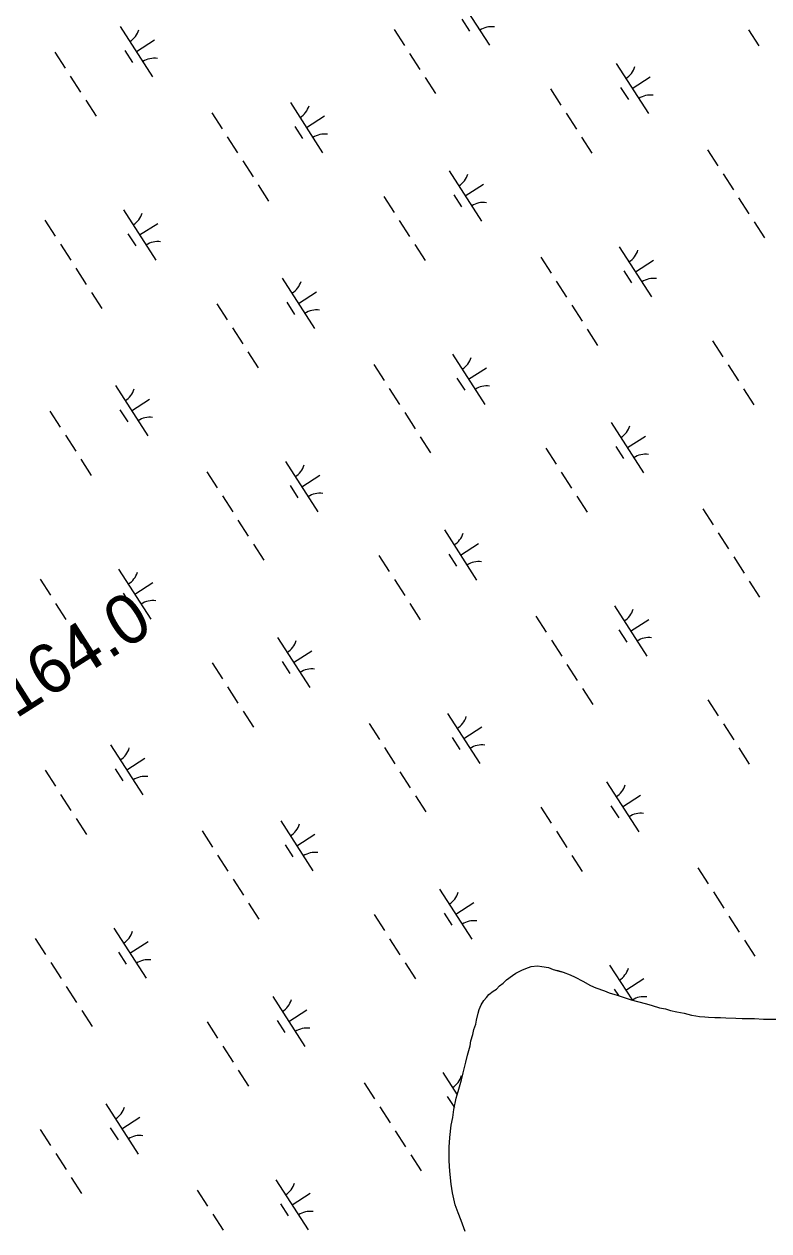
# Model space of a CAD drawing. Extents: x 3937982 to 3958556, y 219448 to 241894.
# Drawn here: x 3952246 to 3952870, y 224641 to 225653 of the extents above; entities that cross this region are included whole.
import ezdxf

# ---------------------------------------------------------------- set-up
doc = ezdxf.new("R2010")
doc.units = 0
for name, color, linetype in [('V-RIVR-RANG-IDEN', 7, 'Continuous'), ('V-TOPO-SHOR', 7, 'Continuous'), ('V-WETL-SWMP', 7, 'Continuous')]:
    doc.layers.add(name, color=color, linetype=linetype)

msp = doc.modelspace()

# ---------------------------------------------------------------- linework, layer by layer
at = {"layer": 'V-TOPO-SHOR'}
for points in [[(3952615.807, 224640.558), (3952612.462, 224649.753), (3952609.79, 224656.321), (3952607.449, 224662.889), (3952605.083, 224673.08), (3952604.053, 224680.314), (3952603.003, 224691.17), (3952602.294, 224699.722), (3952602.226, 224711.242), (3952602.837, 224719.473), (3952604.092, 224729.685), (3952605.37, 224736.275), (3952606.32, 224742.864), (3952608.239, 224752.42), (3952609.851, 224758.025), (3952612.757, 224767.587), (3952614.039, 224773.518), (3952616.292, 224782.419), (3952617.572, 224788.352), (3952619.831, 224796.263), (3952620.464, 224800.545), (3952622.078, 224805.821), (3952623.042, 224809.778), (3952624.66, 224814.394), (3952625.299, 224817.689), (3952626.581, 224823.62), (3952627.552, 224826.59), (3952629.174, 224830.549), (3952631.457, 224834.182), (3952633.745, 224836.83), (3952635.705, 224839.144), (3952639.309, 224842.128), (3952641.933, 224843.789), (3952644.55, 224846.437), (3952647.499, 224848.757), (3952650.446, 224851.41), (3952655.362, 224855.057), (3952658.313, 224857.05), (3952663.232, 224859.712), (3952666.517, 224861.048), (3952671.115, 224862.721)], [(3952671.115, 224862.721), (3952676.376, 224863.411), (3952680.001, 224862.774), (3952685.602, 224861.818), (3952689.561, 224860.196), (3952693.518, 224859.233), (3952697.802, 224857.941), (3952703.742, 224855.672), (3952708.03, 224853.722), (3952714.303, 224850.468), (3952720.908, 224846.886), (3952725.198, 224844.936), (3952732.455, 224842.345), (3952736.413, 224840.723), (3952743.008, 224838.788), (3952747.296, 224837.166), (3952754.878, 224834.907), (3952760.156, 224833.293), (3952767.735, 224831.362), (3952772.352, 224830.072), (3952778.616, 224828.134), (3952783.56, 224827.176), (3952787.847, 224825.883), (3952793.12, 224824.599), (3952799.379, 224823.649), (3952805.312, 224822.037), (3952808.937, 224821.4), (3952812.232, 224820.761), (3952816.513, 224820.456), (3952819.806, 224820.147), (3952825.073, 224819.85), (3952829.681, 224819.877), (3952834.291, 224819.573), (3952842.52, 224819.293), (3952847.79, 224818.996), (3952858.321, 224819.057), (3952865.894, 224818.443), (3952876.097, 224818.502)]]:
    msp.add_lwpolyline(points, dxfattribs=at)
at = {"layer": 'V-WETL-SWMP'}
for p, q in [((3952609.077, 225677.051), (3952636.14, 225635.007)), ((3952612.873, 225656.898), (3952619.368, 225646.808)), ((3952326.644, 225650.711), (3952353.707, 225608.668)), ((3952556.202, 225648.275), (3952564.862, 225634.821)), ((3952853.188, 225648.023), (3952861.848, 225634.569)), ((3952340.175, 225629.69), (3952355.311, 225639.432)), ((3952271.778, 225629.314), (3952280.438, 225615.86)), ((3952330.44, 225630.559), (3952336.935, 225620.468)), ((3952569.192, 225628.094), (3952577.852, 225614.64)), ((3952742.207, 225619.752), (3952769.269, 225577.709)), ((3952284.768, 225609.133), (3952293.428, 225595.68)), ((3952582.182, 225607.913), (3952590.842, 225594.46)), ((3952755.738, 225598.73), (3952770.873, 225608.473)), ((3952687.341, 225598.355), (3952696.001, 225584.901)), ((3952746.003, 225599.6), (3952752.498, 225589.509)), ((3952297.758, 225588.953), (3952306.418, 225575.499)), ((3952469.21, 225587.021), (3952496.273, 225544.978)), ((3952403.345, 225578.426), (3952412.005, 225564.972)), ((3952482.741, 225565.999), (3952497.877, 225575.742)), ((3952700.331, 225578.174), (3952708.99, 225564.72)), ((3952473.006, 225566.869), (3952479.501, 225556.778)), ((3952416.335, 225558.245), (3952424.995, 225544.792)), ((3952713.32, 225557.993), (3952721.98, 225544.54)), ((3952818.908, 225547.467), (3952827.568, 225534.013)), ((3952429.325, 225538.065), (3952437.985, 225524.611)), ((3952602.339, 225529.722), (3952629.402, 225487.679)), ((3952831.897, 225527.286), (3952840.557, 225513.832)), ((3952442.315, 225517.884), (3952450.975, 225504.43)), ((3952615.871, 225508.701), (3952631.006, 225518.443)), ((3952547.473, 225508.325), (3952556.133, 225494.872)), ((3952606.135, 225509.57), (3952612.63, 225499.48)), ((3952844.887, 225507.105), (3952853.547, 225493.652)), ((3952329.343, 225496.992), (3952356.405, 225454.948)), ((3952263.478, 225488.397), (3952272.138, 225474.943)), ((3952342.874, 225475.97), (3952358.01, 225485.712)), ((3952560.463, 225488.145), (3952569.123, 225474.691)), ((3952857.877, 225486.925), (3952866.537, 225473.471)), ((3952333.139, 225476.839), (3952339.634, 225466.749)), ((3952276.468, 225468.216), (3952285.128, 225454.762)), ((3952573.453, 225467.964), (3952582.113, 225454.51)), ((3952744.905, 225466.032), (3952771.968, 225423.989)), ((3952679.04, 225457.437), (3952687.7, 225443.984)), ((3952758.436, 225445.011), (3952773.572, 225454.753)), ((3952289.458, 225448.035), (3952298.118, 225434.581)), ((3952748.701, 225445.88), (3952755.196, 225435.79)), ((3952462.472, 225439.693), (3952489.534, 225397.65)), ((3952692.03, 225437.257), (3952700.69, 225423.803)), ((3952302.448, 225427.854), (3952311.108, 225414.401)), ((3952476.003, 225418.671), (3952491.139, 225428.414)), ((3952407.606, 225418.296), (3952416.266, 225404.842)), ((3952466.268, 225419.541), (3952472.763, 225409.45)), ((3952705.02, 225417.076), (3952713.68, 225403.622)), ((3952420.596, 225398.115), (3952429.256, 225384.661)), ((3952718.01, 225396.895), (3952726.67, 225383.441)), ((3952823.168, 225387.337), (3952831.828, 225373.883)), ((3952433.586, 225377.934), (3952442.246, 225364.481)), ((3952605.038, 225376.003), (3952632.1, 225333.96)), ((3952539.173, 225367.408), (3952547.833, 225353.954)), ((3952618.569, 225354.981), (3952633.705, 225364.724)), ((3952836.158, 225367.156), (3952844.818, 225353.702)), ((3952608.834, 225355.85), (3952615.329, 225345.76)), ((3952322.605, 225349.663), (3952349.667, 225307.62)), ((3952552.163, 225347.227), (3952560.823, 225333.773)), ((3952849.148, 225346.975), (3952857.808, 225333.521)), ((3952336.136, 225328.642), (3952351.272, 225338.384)), ((3952267.739, 225328.266), (3952276.399, 225314.813)), ((3952326.401, 225329.511), (3952332.896, 225319.421)), ((3952565.153, 225327.046), (3952573.813, 225313.593)), ((3952738.167, 225318.704), (3952765.23, 225276.661)), ((3952280.729, 225308.086), (3952289.389, 225294.632)), ((3952578.143, 225306.866), (3952586.803, 225293.412)), ((3952751.698, 225297.683), (3952766.834, 225307.425)), ((3952683.301, 225297.307), (3952691.961, 225283.853)), ((3952741.963, 225298.552), (3952748.458, 225288.461)), ((3952293.719, 225287.905), (3952302.379, 225274.451)), ((3952465.171, 225285.973), (3952492.233, 225243.93)), ((3952399.306, 225277.378), (3952407.966, 225263.925)), ((3952478.702, 225264.952), (3952493.837, 225274.694)), ((3952696.291, 225277.126), (3952704.951, 225263.673)), ((3952468.967, 225265.821), (3952475.462, 225255.731)), ((3952412.296, 225257.198), (3952420.956, 225243.744)), ((3952709.281, 225256.946), (3952717.941, 225243.492)), ((3952814.868, 225246.419), (3952823.528, 225232.965)), ((3952425.286, 225237.017), (3952433.946, 225223.563)), ((3952598.3, 225228.675), (3952625.362, 225186.632)), ((3952827.858, 225226.238), (3952836.518, 225212.785)), ((3952438.275, 225216.836), (3952446.935, 225203.382)), ((3952611.831, 225207.653), (3952626.967, 225217.396)), ((3952543.434, 225207.278), (3952552.094, 225193.824)), ((3952602.096, 225208.522), (3952608.591, 225198.432)), ((3952840.848, 225206.058), (3952849.508, 225192.604)), ((3952325.304, 225195.944), (3952352.366, 225153.901)), ((3952259.439, 225187.349), (3952268.098, 225173.895)), ((3952338.835, 225174.922), (3952353.97, 225184.665)), ((3952556.424, 225187.097), (3952565.084, 225173.643)), ((3952853.838, 225185.877), (3952862.498, 225172.423)), ((3952329.1, 225175.791), (3952335.594, 225165.701)), ((3952272.428, 225167.168), (3952281.088, 225153.714)), ((3952569.414, 225166.916), (3952578.074, 225153.462)), ((3952740.866, 225164.985), (3952767.928, 225122.941)), ((3952675.001, 225156.39), (3952683.661, 225142.936)), ((3952754.397, 225143.963), (3952769.533, 225153.705)), ((3952285.418, 225146.987), (3952294.078, 225133.534)), ((3952458.433, 225138.645), (3952485.495, 225096.602)), ((3952744.662, 225144.832), (3952751.157, 225134.742)), ((3952687.991, 225136.209), (3952696.651, 225122.755)), ((3952298.408, 225126.807), (3952307.068, 225113.353)), ((3952462.229, 225118.493), (3952468.724, 225108.402)), ((3952471.964, 225117.624), (3952487.099, 225127.366)), ((3952403.567, 225117.248), (3952412.227, 225103.794)), ((3952700.981, 225116.028), (3952709.641, 225102.574)), ((3952416.557, 225097.067), (3952425.217, 225083.614)), ((3952713.971, 225095.847), (3952722.631, 225082.394)), ((3952819.129, 225086.289), (3952827.789, 225072.835)), ((3952429.547, 225076.887), (3952438.206, 225063.433)), ((3952600.999, 225074.955), (3952628.061, 225032.912)), ((3952535.134, 225066.36), (3952543.794, 225052.906)), ((3952614.53, 225053.933), (3952629.665, 225063.676)), ((3952832.119, 225066.108), (3952840.779, 225052.654)), ((3952318.565, 225048.616), (3952345.628, 225006.572)), ((3952604.795, 225054.803), (3952611.29, 225044.712)), ((3952332.097, 225027.594), (3952347.232, 225037.337)), ((3952548.124, 225046.179), (3952556.783, 225032.726)), ((3952845.109, 225045.927), (3952853.769, 225032.474)), ((3952263.699, 225027.219), (3952272.359, 225013.765)), ((3952322.361, 225028.463), (3952328.856, 225018.373)), ((3952561.113, 225025.999), (3952569.773, 225012.545)), ((3952734.128, 225017.656), (3952761.19, 224975.613)), ((3952276.689, 225007.038), (3952285.349, 224993.584)), ((3952747.659, 224996.635), (3952762.795, 225006.377)), ((3952574.103, 225005.818), (3952582.763, 224992.364)), ((3952679.262, 224996.259), (3952687.922, 224982.806)), ((3952737.924, 224997.504), (3952744.419, 224987.414)), ((3952289.679, 224986.857), (3952298.339, 224973.403)), ((3952395.266, 224976.331), (3952403.926, 224962.877)), ((3952461.131, 224984.926), (3952488.194, 224942.882)), ((3952692.252, 224976.079), (3952700.912, 224962.625)), ((3952474.663, 224963.904), (3952489.798, 224973.646)), ((3952408.256, 224956.15), (3952416.916, 224942.696)), ((3952464.927, 224964.773), (3952471.422, 224954.683)), ((3952705.242, 224955.898), (3952713.902, 224942.444)), ((3952421.246, 224935.969), (3952429.906, 224922.515)), ((3952810.829, 224945.371), (3952819.489, 224931.918)), ((3952594.261, 224927.627), (3952621.323, 224885.584)), ((3952434.236, 224915.788), (3952442.896, 224902.335)), ((3952607.792, 224906.605), (3952622.927, 224916.348)), ((3952823.819, 224925.191), (3952832.479, 224911.737)), ((3952539.395, 224906.23), (3952548.054, 224892.776)), ((3952598.057, 224907.475), (3952604.552, 224897.384)), ((3952836.809, 224905.01), (3952845.468, 224891.556)), ((3952255.399, 224886.301), (3952264.059, 224872.847)), ((3952321.264, 224894.896), (3952348.326, 224852.853)), ((3952552.384, 224886.049), (3952561.044, 224872.595)), ((3952334.795, 224873.874), (3952349.931, 224883.617)), ((3952849.798, 224884.829), (3952858.458, 224871.375)), ((3952268.389, 224866.12), (3952277.049, 224852.667)), ((3952325.06, 224874.744), (3952331.555, 224864.653)), ((3952565.374, 224865.868), (3952574.034, 224852.415)), ((3952650.446, 224851.409), (3952655.361, 224855.058)), ((3952655.361, 224855.058), (3952658.312, 224857.05)), ((3952658.312, 224857.05), (3952663.233, 224859.712)), ((3952663.233, 224859.712), (3952666.517, 224861.048)), ((3952666.517, 224861.048), (3952671.115, 224862.721)), ((3952671.115, 224862.721), (3952676.377, 224863.41)), ((3952676.377, 224863.41), (3952680.001, 224862.773)), ((3952680.001, 224862.773), (3952685.602, 224861.818)), ((3952685.602, 224861.818), (3952689.561, 224860.196)), ((3952689.561, 224860.196), (3952693.517, 224859.232)), ((3952693.517, 224859.232), (3952697.803, 224857.94)), ((3952697.803, 224857.94), (3952703.741, 224855.671)), ((3952703.741, 224855.671), (3952708.031, 224853.722)), ((3952736.826, 224863.937), (3952755.668, 224834.666)), ((3952281.379, 224845.94), (3952290.039, 224832.486)), ((3952641.933, 224843.789), (3952644.55, 224846.437)), ((3952644.55, 224846.437), (3952647.499, 224848.758)), ((3952647.499, 224848.758), (3952650.446, 224851.409)), ((3952708.031, 224853.722), (3952714.304, 224850.467)), ((3952714.304, 224850.467), (3952720.908, 224846.885)), ((3952720.908, 224846.885), (3952725.198, 224844.936)), ((3952725.198, 224844.936), (3952732.454, 224842.345)), ((3952750.358, 224842.915), (3952765.493, 224852.658)), ((3952454.393, 224837.597), (3952481.456, 224795.554)), ((3952631.457, 224834.182), (3952633.745, 224836.829)), ((3952633.745, 224836.829), (3952635.706, 224839.144)), ((3952635.706, 224839.144), (3952639.309, 224842.128)), ((3952639.309, 224842.128), (3952641.933, 224843.789)), ((3952732.454, 224842.345), (3952736.413, 224840.723)), ((3952736.413, 224840.723), (3952743.007, 224838.787)), ((3952740.622, 224843.784), (3952744.107, 224838.371)), ((3952743.007, 224838.787), (3952747.296, 224837.166)), ((3952747.296, 224837.166), (3952754.879, 224834.907)), ((3952754.879, 224834.907), (3952760.155, 224833.292)), ((3952294.369, 224825.759), (3952303.029, 224812.305)), ((3952467.924, 224816.576), (3952483.06, 224826.318)), ((3952626.582, 224823.621), (3952627.552, 224826.589)), ((3952627.552, 224826.589), (3952629.174, 224830.548)), ((3952629.174, 224830.548), (3952631.457, 224834.182)), ((3952760.155, 224833.292), (3952767.736, 224831.362)), ((3952767.736, 224831.362), (3952772.352, 224830.072)), ((3952772.352, 224830.072), (3952778.617, 224828.134)), ((3952778.617, 224828.134), (3952783.56, 224827.176)), ((3952783.56, 224827.176), (3952787.846, 224825.884)), ((3952787.846, 224825.884), (3952793.12, 224824.599)), ((3952793.12, 224824.599), (3952799.379, 224823.648)), ((3952399.527, 224816.2), (3952408.187, 224802.747)), ((3952458.189, 224817.445), (3952464.684, 224807.355)), ((3952623.042, 224809.777), (3952624.661, 224814.394)), ((3952624.661, 224814.394), (3952625.3, 224817.689)), ((3952625.3, 224817.689), (3952626.582, 224823.621)), ((3952799.379, 224823.648), (3952805.313, 224822.037)), ((3952805.313, 224822.037), (3952808.937, 224821.4)), ((3952808.937, 224821.4), (3952812.232, 224820.761)), ((3952812.232, 224820.761), (3952816.513, 224820.457)), ((3952816.513, 224820.457), (3952819.806, 224820.147)), ((3952819.806, 224820.147), (3952825.074, 224819.849)), ((3952825.074, 224819.849), (3952829.682, 224819.876)), ((3952829.682, 224819.876), (3952834.291, 224819.574)), ((3952834.291, 224819.574), (3952842.521, 224819.293)), ((3952842.521, 224819.293), (3952847.789, 224818.995)), ((3952847.789, 224818.995), (3952858.321, 224819.057)), ((3952858.321, 224819.057), (3952865.895, 224818.443)), ((3952865.895, 224818.443), (3952876.098, 224818.503)), ((3952620.463, 224800.546), (3952622.078, 224805.821)), ((3952622.078, 224805.821), (3952623.042, 224809.777)), ((3952412.517, 224796.02), (3952421.177, 224782.566)), ((3952617.573, 224788.351), (3952619.83, 224796.263)), ((3952619.83, 224796.263), (3952620.463, 224800.546)), ((3952616.291, 224782.419), (3952617.573, 224788.351)), ((3952425.507, 224775.839), (3952434.167, 224762.385)), ((3952596.959, 224773.907), (3952609.027, 224755.159)), ((3952614.039, 224773.519), (3952616.291, 224782.419)), ((3952531.094, 224765.312), (3952539.754, 224751.859)), ((3952609.851, 224758.025), (3952612.758, 224767.587)), ((3952612.758, 224767.587), (3952614.039, 224773.519)), ((3952600.755, 224753.755), (3952606.664, 224744.576)), ((3952608.239, 224752.42), (3952609.851, 224758.025)), ((3952314.526, 224747.568), (3952341.588, 224705.525)), ((3952544.084, 224745.132), (3952552.744, 224731.678)), ((3952606.32, 224742.864), (3952608.239, 224752.42)), ((3952328.057, 224726.546), (3952343.193, 224736.289)), ((3952604.093, 224729.685), (3952605.371, 224736.275)), ((3952605.371, 224736.275), (3952606.32, 224742.864)), ((3952259.66, 224726.171), (3952268.32, 224712.717)), ((3952318.322, 224727.416), (3952324.817, 224717.325)), ((3952557.074, 224724.951), (3952565.734, 224711.497)), ((3952602.837, 224719.474), (3952604.093, 224729.685)), ((3952602.227, 224711.242), (3952602.837, 224719.474)), ((3952272.65, 224705.99), (3952281.31, 224692.536)), ((3952570.064, 224704.77), (3952578.724, 224691.316)), ((3952602.294, 224699.723), (3952602.227, 224711.242)), ((3952603.003, 224691.17), (3952602.294, 224699.723)), ((3952285.64, 224685.809), (3952294.3, 224672.356)), ((3952457.092, 224683.878), (3952484.154, 224641.835)), ((3952604.054, 224680.314), (3952603.003, 224691.17)), ((3952391.227, 224675.283), (3952399.887, 224661.829)), ((3952470.623, 224662.856), (3952485.759, 224672.599)), ((3952605.084, 224673.079), (3952604.054, 224680.314)), ((3952607.448, 224662.89), (3952605.084, 224673.079)), ((3952460.888, 224663.725), (3952467.383, 224653.635)), ((3952609.79, 224656.321), (3952607.448, 224662.89)), ((3952404.217, 224655.102), (3952412.877, 224641.648)), ((3952612.462, 224649.754), (3952609.79, 224656.321)), ((3952615.807, 224640.557), (3952612.462, 224649.754))]:
    msp.add_line(p, q, dxfattribs=at)
for centre, start, end in [((3952325.425, 225653.044), 301.99668, 343.540338), ((3952637.758, 225632.932), 81.996677, 123.540335), ((3952355.325, 225606.592), 81.996677, 123.540335), ((3952740.987, 225622.085), 301.99668, 343.540338), ((3952770.887, 225575.633), 81.996677, 123.540335), ((3952467.991, 225589.354), 301.99668, 343.540338), ((3952497.891, 225542.902), 81.996677, 123.540335), ((3952601.12, 225532.055), 301.99668, 343.540338), ((3952631.02, 225485.603), 81.996677, 123.540335), ((3952328.124, 225499.324), 301.99668, 343.540338), ((3952358.024, 225452.873), 81.996677, 123.540335), ((3952743.686, 225468.365), 301.99668, 343.540338), ((3952461.253, 225442.026), 301.99668, 343.540338), ((3952773.586, 225421.913), 81.996677, 123.540335), ((3952491.153, 225395.574), 81.996677, 123.540335), ((3952603.819, 225378.336), 301.99668, 343.540338), ((3952321.386, 225351.996), 301.99668, 343.540338), ((3952633.719, 225331.884), 81.996677, 123.540335), ((3952351.286, 225305.544), 81.996677, 123.540335), ((3952736.948, 225321.037), 301.99668, 343.540338), ((3952766.848, 225274.585), 81.996677, 123.540335), ((3952463.952, 225288.306), 301.99668, 343.540338), ((3952493.852, 225241.854), 81.996677, 123.540335), ((3952597.081, 225231.008), 301.99668, 343.540338), ((3952626.981, 225184.556), 81.996677, 123.540335), ((3952324.084, 225198.277), 301.99668, 343.540338), ((3952353.984, 225151.825), 81.996677, 123.540335), ((3952739.647, 225167.317), 301.99668, 343.540338), ((3952769.547, 225120.866), 81.996677, 123.540335), ((3952457.214, 225140.978), 301.99668, 343.540338), ((3952487.114, 225094.526), 81.996677, 123.540335), ((3952599.779, 225077.288), 301.99668, 343.540338), ((3952629.679, 225030.836), 81.996677, 123.540335), ((3952317.346, 225050.949), 301.99668, 343.540338), ((3952347.246, 225004.497), 81.996677, 123.540335), ((3952732.909, 225019.989), 301.99668, 343.540338), ((3952762.809, 224973.537), 81.996677, 123.540335), ((3952459.912, 224987.258), 301.99668, 343.540338), ((3952489.812, 224940.807), 81.996677, 123.540335), ((3952593.041, 224929.96), 301.99668, 343.540338), ((3952622.941, 224883.508), 81.996677, 123.540335), ((3952320.045, 224897.229), 301.99668, 343.540338), ((3952349.945, 224850.777), 81.996677, 123.540335), ((3952735.607, 224866.27), 301.99668, 343.540338), ((3952453.174, 224839.93), 301.99668, 343.540338), ((3952765.507, 224819.818), 81.996677, 123.024604), ((3952483.074, 224793.478), 81.996677, 123.540335), ((3952595.74, 224776.24), 301.99668, 343.540338), ((3952313.307, 224749.901), 301.99668, 343.540338), ((3952343.207, 224703.449), 81.996677, 123.540335), ((3952455.873, 224686.211), 301.99668, 343.540338), ((3952485.773, 224639.759), 81.996677, 123.540335)]:
    msp.add_arc(centre, 17.623, start, end, dxfattribs=at)

# ---------------------------------------------------------------- texts
at = {"layer": 'V-RIVR-RANG-IDEN'}
msp.add_text('R-164.0', height=41.5, rotation=32.455496, dxfattribs=at).set_placement((3952189.656, 225038.617))

doc.saveas('drawing.dxf')
